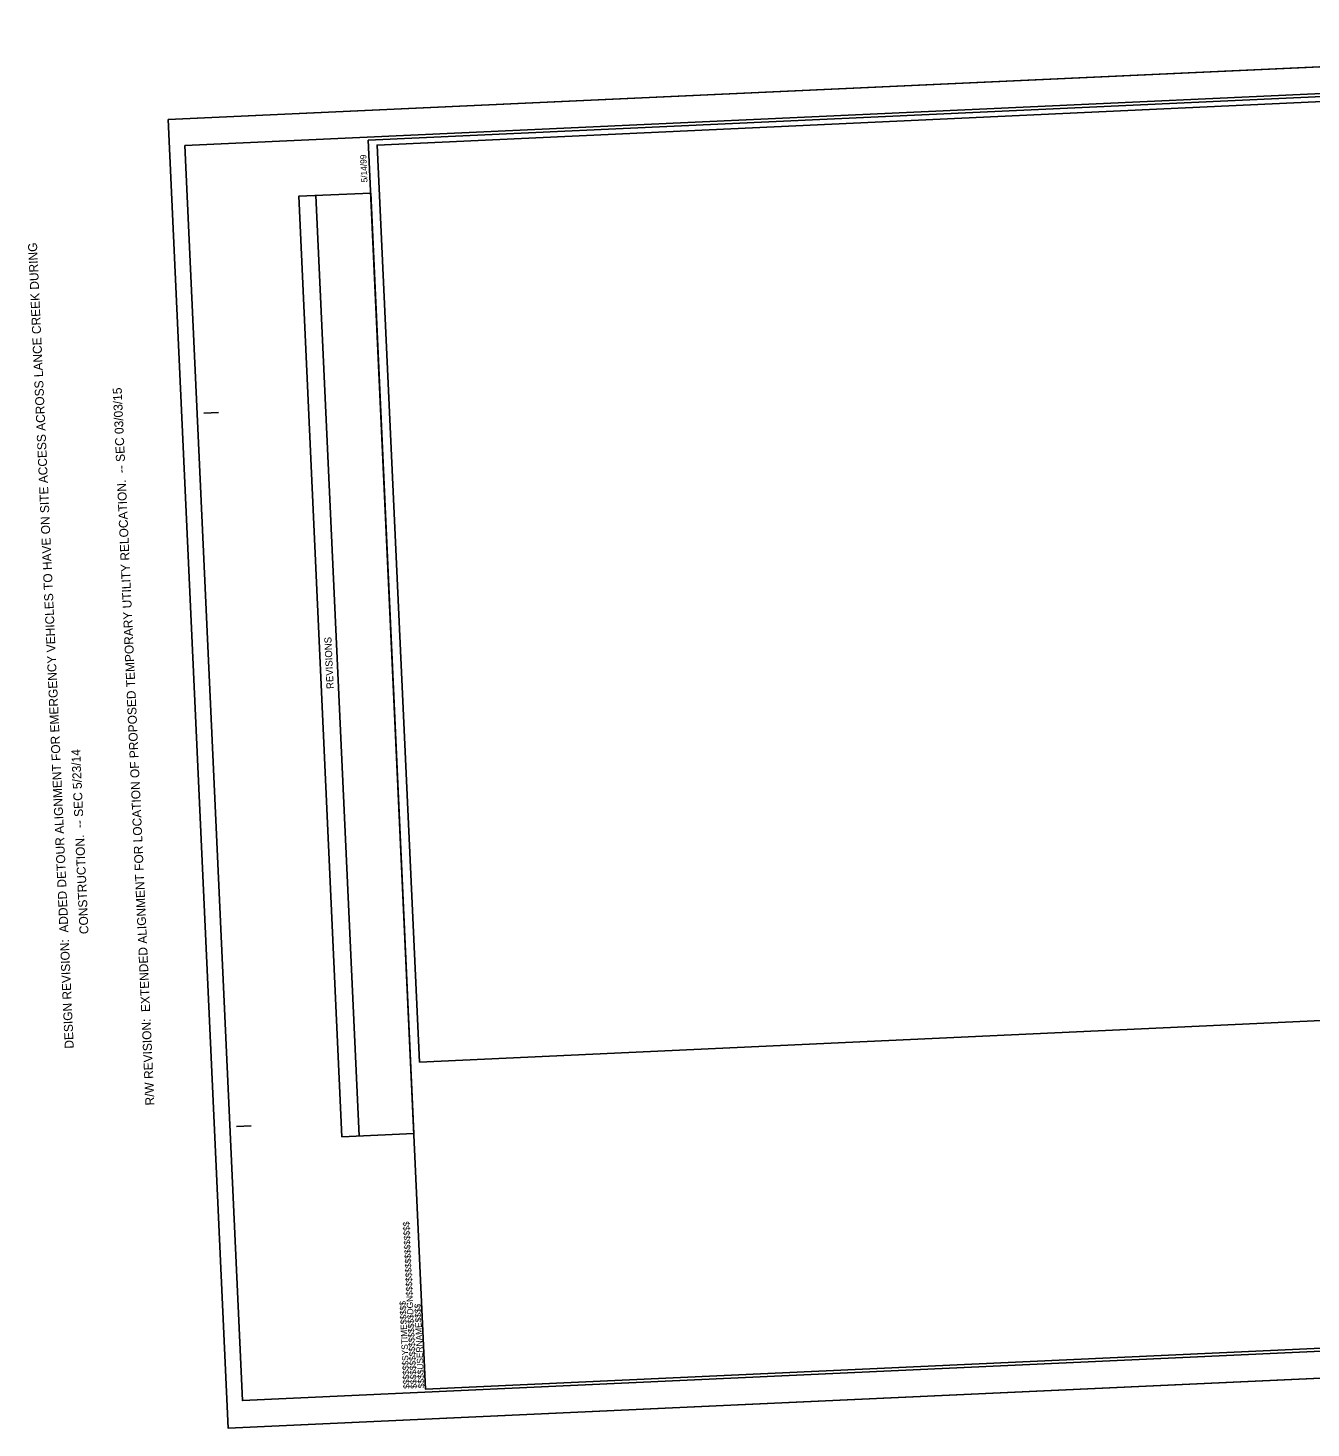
# Model space of a CAD drawing. Extents: x 1191070 to 1191932, y 892813 to 893283.
# Drawn here: x 1191069.8 to 1191500.7, y 892813.1 to 893283.5 of the extents above; entities that cross this region are included whole.
import ezdxf

# ---------------------------------------------------------------- set-up
doc = ezdxf.new("R2010")
doc.units = 0
for name, color, linetype in [('Prop DSN Text', 7, 'Continuous'), ('Sheet Block Revision CELL', 7, 'Continuous'), ('Sheet Border Standard 30in CELL', 7, 'Continuous'), ('Sheet Clip Boundary CELL', 7, 'Continuous'), ('Sheet Cutting Line CELL', 7, 'Continuous'), ('Sheet Plot Border Inside CELL', 7, 'Continuous'), ('Sheet Plot Border Outside CELL', 7, 'Continuous')]:
    doc.layers.add(name, color=color, linetype=linetype)

msp = doc.modelspace()

# ---------------------------------------------------------------- linework, layer by layer
at = {"layer": 'Sheet Block Revision CELL'}
msp.add_line((1191181, 892911.25), (1191166.54, 893227.18), dxfattribs=at)
msp.add_lwpolyline([(1191175.18, 892910.99), (1191160.73, 893226.92), (1191184.92, 893228.03), (1191199.38, 892912.1)], close=True, dxfattribs=at)
at = {"layer": 'Sheet Border Standard 30in CELL'}
for p, q in [((1191184.51, 893245.76), (1191184.51, 893245.76)), ((1191128.84, 893154.12), (1191133.84, 893154.35)), ((1191139.81, 892914.38), (1191144.8, 892914.6))]:
    msp.add_line(p, q, dxfattribs=at)
msp.add_lwpolyline([(1191783.48, 893273.17), (1191184.11, 893245.75), (1191203.31, 892826.19), (1191802.68, 892853.61)], close=True, dxfattribs=at)
at = {"layer": 'Sheet Clip Boundary CELL'}
msp.add_lwpolyline([(1191201.31, 892936.07), (1191187.08, 893244.15), (1191703.39, 893267.99), (1191706.1, 893208.66), (1191782.81, 893212.17), (1191794.3, 892963.46), (1191451.08, 892947.61)], close=True, dxfattribs=at)
at = {"layer": 'Sheet Cutting Line CELL'}
for p, q in [((1191789.82, 893283.47), (1191116.92, 893252.68)), ((1191116.92, 893252.68), (1191137.03, 892813.14)), ((1191137.03, 892813.14), (1191809.93, 892843.93))]:
    msp.add_line(p, q, dxfattribs=at)
at = {"layer": 'Sheet Plot Border Inside CELL'}
msp.add_lwpolyline([(1191788.43, 893274.42), (1191122.53, 893243.95), (1191141.82, 892822.35), (1191807.72, 892852.82)], close=True, dxfattribs=at)
at = {"layer": 'Sheet Plot Border Outside CELL'}
msp.add_lwpolyline([(1191789.82, 893283.47), (1191116.92, 893252.68), (1191137.03, 892813.14), (1191809.93, 892843.93)], close=True, dxfattribs=at)

# ---------------------------------------------------------------- texts
at = {"layer": 'Prop DSN Text'}
for s, p in [('DESIGN REVISION:  ADDED DETOUR ALIGNMENT FOR EMERGENCY VEHICLES TO HAVE ON SITE ACCESS ACROSS LANCE CREEK DURING', (1191085.21, 892940.66)), ('R/W REVISION:  EXTENDED ALIGNMENT FOR LOCATION OF PROPOSED TEMPORARY UTILITY RELOCATION.  -- SEC 03/03/15 ', (1191112.3, 892921.57)), ('CONSTRUCTION.  -- SEC 5/23/14 ', (1191090.18, 892979.13))]:
    msp.add_text(s, height=3, rotation=92.6195, dxfattribs=at).set_placement(p)
at = {"layer": 'Sheet Block Revision CELL'}
msp.add_text('REVISIONS', height=2.4, rotation=92.6195, dxfattribs=at).set_placement((1191172.5, 893061.48))
at = {"layer": 'Sheet Border Standard 30in CELL'}
for s, p in [('5/14/99', (1191183.86, 893231.64)), ('$$$$$$$$$$$$$$$$DGN$$$$$$$$$$$$$$$$', (1191200.43, 892826.39)), ('$$$$$$SYSTIME$$$$$', (1191198.01, 892826.36)), ('$$$$USERNAME$$$$', (1191202.95, 892826.55))]:
    msp.add_text(s, height=2.1, rotation=92.6195, dxfattribs=at).set_placement(p)

doc.saveas('drawing.dxf')
